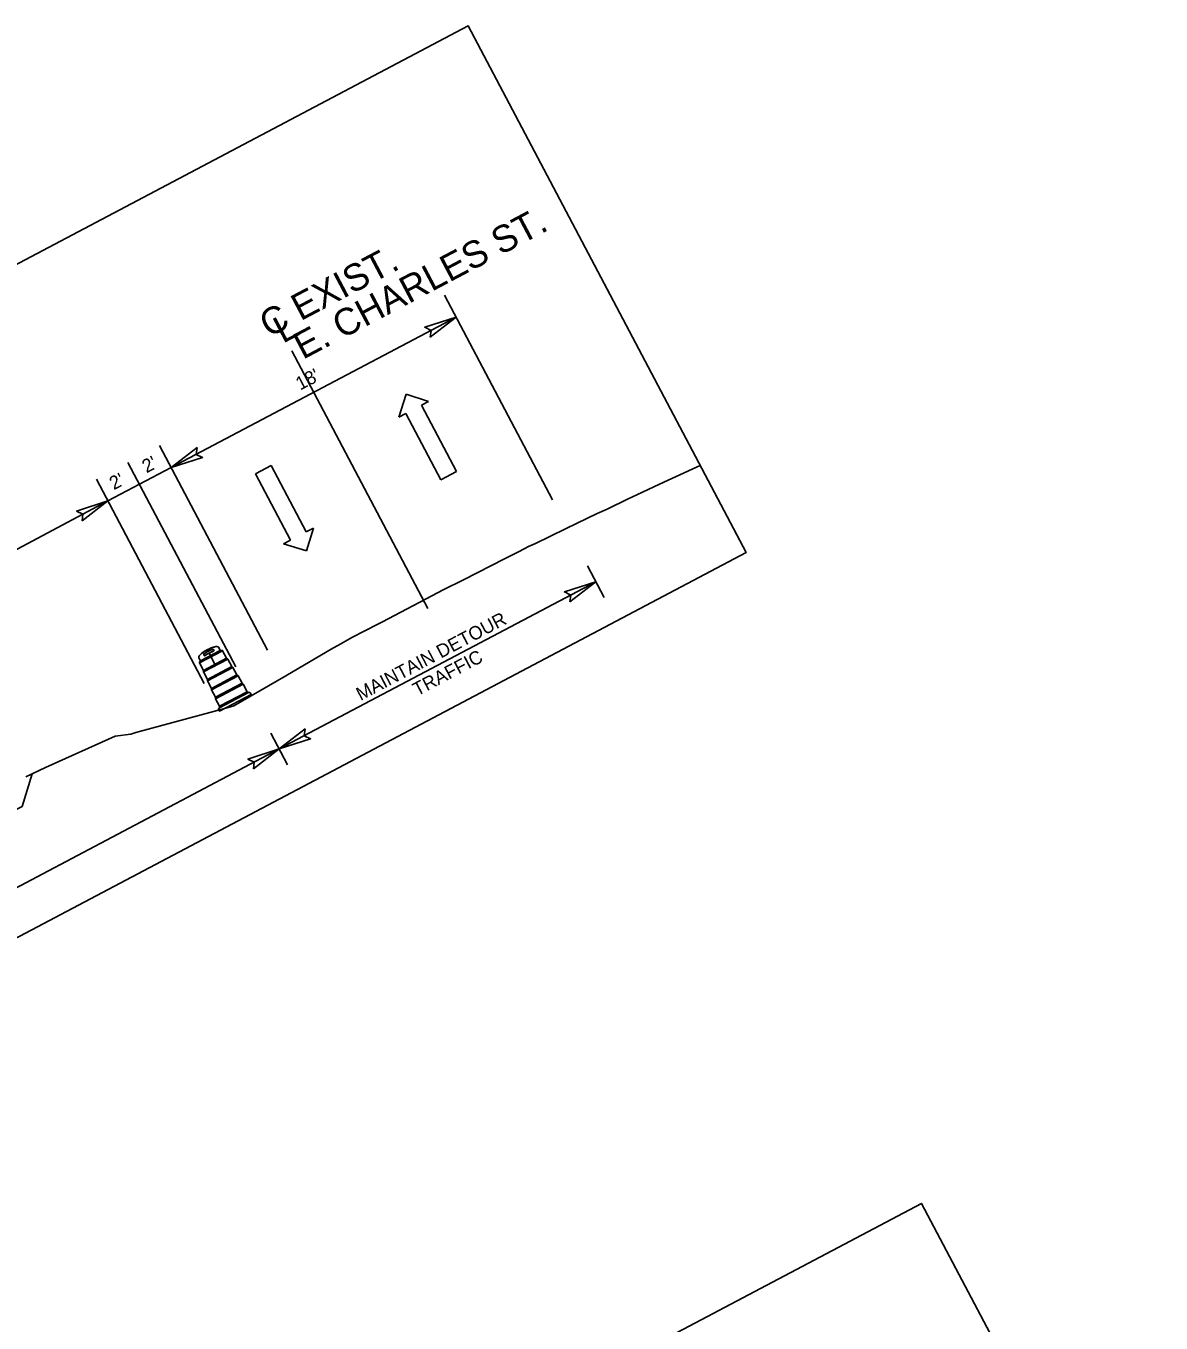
# Model space of a CAD drawing. Extents: x 1487176 to 1495274, y 497106 to 503692.
# Drawn here: x 1488752.5 to 1488815.9, y 497172.6 to 497245.1 of the extents above; entities that cross this region are included whole.
import ezdxf

# ---------------------------------------------------------------- set-up
doc = ezdxf.new("R2010")
doc.units = 0
for name, color, linetype in [('Default', 7, 'Continuous'), ('Exist XS Ground Line', 7, 'Continuous'), ('Prop Terminator CELL', 7, 'Continuous'), ('Typical Hinge Slope Interstate CELL', 7, 'Continuous'), ('WZ OSDR CELL', 7, 'Continuous')]:
    doc.layers.add(name, color=color, linetype=linetype)

msp = doc.modelspace()

# ---------------------------------------------------------------- linework, layer by layer
at = {"layer": 'Default'}
for p, q in [((1488781.918, 497218.598), (1488775.886, 497230.022)), ((1488776.533, 497228.797), (1488760.616, 497220.392)), ((1488774.953, 497212.514), (1488767.352, 497226.91)), ((1488773.735, 497224.49), (1488773.327, 497223.207)), ((1488774.999, 497224.089), (1488773.735, 497224.49)), ((1488774.601, 497223.879), (1488774.999, 497224.089)), ((1488776.562, 497220.165), (1488774.601, 497223.879)), ((1488773.327, 497223.207), (1488773.725, 497223.417)), ((1488773.725, 497223.417), (1488775.686, 497219.703)), ((1488766.001, 497210.193), (1488759.969, 497221.617)), ((1488764.232, 497209.259), (1488758.2, 497220.683)), ((1488758.847, 497219.459), (1488760.616, 497220.392)), ((1488765.325, 497220.05), (1488766.201, 497220.512)), ((1488767.286, 497216.336), (1488765.325, 497220.05)), ((1488766.201, 497220.512), (1488768.162, 497216.798)), ((1488775.686, 497219.703), (1488776.562, 497220.165)), ((1488762.464, 497208.325), (1488756.432, 497219.749)), ((1488757.078, 497218.525), (1488758.847, 497219.459)), ((1488757.078, 497218.525), (1488745.582, 497212.455)), ((1488766.888, 497216.126), (1488767.286, 497216.336)), ((1488768.162, 497216.798), (1488768.56, 497217.008)), ((1488768.56, 497217.008), (1488768.179, 497215.738)), ((1488768.179, 497215.738), (1488766.888, 497216.126)), ((1488784.808, 497213.125), (1488783.874, 497214.893)), ((1488784.341, 497214.009), (1488766.655, 497204.671)), ((1488767.122, 497203.786), (1488766.188, 497205.555)), ((1488766.655, 497204.671), (1488692.227, 497165.371))]:
    msp.add_line(p, q, dxfattribs=at)
for points in [[(1488676.518, 497191.898), (1488777.216, 497245.069), (1488792.751, 497215.648), (1488692.053, 497162.477)], [(1488710.97, 497130.93), (1488802.537, 497179.28), (1488815.927, 497153.921), (1488724.36, 497105.571)]]:
    msp.add_lwpolyline(points, close=True, dxfattribs=at)
msp.add_lwpolyline([(1488749.342, 497199.978), (1488752.289, 497201.459), (1488752.849, 497203.272)], dxfattribs=at)
at = {"layer": 'Exist XS Ground Line'}
msp.add_lwpolyline([(1488752.498, 497203.103), (1488753.584, 497203.626), (1488757.485, 497205.384), (1488758.354, 497205.487), (1488758.644, 497205.585), (1488763.673, 497206.94), (1488764.111, 497207.085), (1488767.017, 497208.753), (1488769.641, 497210.295), (1488769.971, 497210.474), (1488770.715, 497210.901), (1488772.153, 497211.635), (1488772.425, 497211.774), (1488773.09, 497212.124), (1488774.122, 497212.668), (1488774.541, 497212.89), (1488775.82, 497213.561), (1488776.94, 497214.124), (1488779.245, 497215.294), (1488780.067, 497215.709), (1488780.581, 497215.973), (1488780.962, 497216.15), (1488781.769, 497216.538), (1488782.693, 497216.983), (1488784.423, 497217.817), (1488784.967, 497218.076), (1488786.156, 497218.643), (1488786.64, 497218.872), (1488787.893, 497219.464), (1488788.585, 497219.789), (1488790.181, 497220.516)], dxfattribs=at)
at = {"layer": 'Prop Terminator CELL'}
for points in [[(1488775.086, 497227.682), (1488776.533, 497228.797), (1488774.783, 497228.235), (1488775.136, 497228.059)], [(1488762.062, 497221.507), (1488760.616, 497220.392), (1488762.366, 497220.955), (1488762.013, 497221.13)], [(1488755.631, 497217.41), (1488757.078, 497218.525), (1488755.328, 497217.962), (1488755.681, 497217.787)], [(1488782.894, 497212.895), (1488784.341, 497214.009), (1488782.591, 497213.447), (1488782.944, 497213.271)], [(1488768.102, 497205.785), (1488766.655, 497204.671), (1488768.405, 497205.233), (1488768.052, 497205.408)], [(1488765.208, 497203.556), (1488766.655, 497204.671), (1488764.905, 497204.108), (1488765.258, 497203.933)]]:
    msp.add_lwpolyline(points, close=True, dxfattribs=at)
at = {"layer": 'WZ OSDR CELL'}
for p, q in [((1488762.193, 497209.475), (1488763.489, 497210.159)), ((1488762.25, 497209.594), (1488763.359, 497210.179)), ((1488762.437, 497209.911), (1488762.434, 497209.917)), ((1488762.992, 497210.204), (1488762.989, 497210.209)), ((1488763.359, 497210.179), (1488763.291, 497210.309)), ((1488763.489, 497210.159), (1488763.709, 497209.744)), ((1488762.25, 497209.594), (1488762.182, 497209.723)), ((1488762.193, 497209.475), (1488762.413, 497209.059)), ((1488762.413, 497209.059), (1488763.709, 497209.744)), ((1488762.418, 497208.973), (1488763.777, 497209.691)), ((1488762.637, 497208.558), (1488763.996, 497209.275)), ((1488762.643, 497208.472), (1488764.064, 497209.223)), ((1488763.709, 497209.744), (1488763.777, 497209.691)), ((1488763.777, 497209.691), (1488763.996, 497209.275)), ((1488763.996, 497209.275), (1488764.064, 497209.223)), ((1488764.064, 497209.223), (1488764.284, 497208.807)), ((1488762.413, 497209.059), (1488762.418, 497208.973)), ((1488762.418, 497208.973), (1488762.637, 497208.558)), ((1488762.637, 497208.558), (1488762.643, 497208.472)), ((1488762.643, 497208.472), (1488762.862, 497208.056)), ((1488762.862, 497208.056), (1488764.284, 497208.807)), ((1488762.867, 497207.97), (1488764.352, 497208.754)), ((1488764.284, 497208.807), (1488764.352, 497208.754)), ((1488764.352, 497208.754), (1488764.571, 497208.339)), ((1488762.862, 497208.056), (1488762.867, 497207.97)), ((1488762.867, 497207.97), (1488763.087, 497207.555)), ((1488763.087, 497207.555), (1488764.571, 497208.339)), ((1488763.092, 497207.469), (1488764.639, 497208.286)), ((1488763.307, 497206.963), (1488764.936, 497207.822)), ((1488763.311, 497207.053), (1488764.859, 497207.87)), ((1488763.311, 497206.787), (1488765.078, 497207.72)), ((1488764.571, 497208.339), (1488764.639, 497208.286)), ((1488764.639, 497208.286), (1488764.859, 497207.87)), ((1488764.859, 497207.87), (1488764.927, 497207.818)), ((1488765.078, 497207.72), (1488765.042, 497207.79)), ((1488763.087, 497207.555), (1488763.092, 497207.469)), ((1488763.092, 497207.469), (1488763.311, 497207.053)), ((1488763.312, 497207.053), (1488763.317, 497206.967)), ((1488763.311, 497206.787), (1488763.275, 497206.857))]:
    msp.add_line(p, q, dxfattribs=at)
for points in [[(1488762.418, 497208.973), (1488763.097, 497209.332), (1488762.731, 497210.025), (1488762.698, 497210.008), (1488762.673, 497209.992), (1488762.647, 497209.978), (1488762.62, 497209.961), (1488762.592, 497209.943), (1488762.563, 497209.923), (1488762.531, 497209.902), (1488762.511, 497209.887), (1488762.497, 497209.882), (1488762.484, 497209.882), (1488762.47, 497209.884), (1488762.459, 497209.889), (1488762.449, 497209.896), (1488762.441, 497209.904), (1488762.431, 497209.923), (1488762.428, 497209.935), (1488762.429, 497209.95), (1488762.433, 497209.964), (1488762.441, 497209.978), (1488762.45, 497209.986), (1488762.474, 497210.003), (1488762.505, 497210.025), (1488762.571, 497210.069), (1488762.62, 497210.098), (1488762.657, 497210.118), (1488762.677, 497210.129), (1488762.631, 497210.216), (1488762.595, 497210.197), (1488762.549, 497210.171), (1488762.503, 497210.143), (1488762.455, 497210.111), (1488762.411, 497210.079), (1488762.363, 497210.043), (1488762.31, 497210), (1488762.279, 497209.973), (1488762.231, 497209.928), (1488762.21, 497209.908), (1488762.198, 497209.894), (1488762.186, 497209.877), (1488762.176, 497209.858), (1488762.168, 497209.831), (1488762.164, 497209.808), (1488762.164, 497209.788), (1488762.167, 497209.767), (1488762.172, 497209.747), (1488762.182, 497209.723), (1488762.25, 497209.594), (1488762.241, 497209.582), (1488762.232, 497209.569), (1488762.22, 497209.549), (1488762.21, 497209.528), (1488762.202, 497209.508), (1488762.193, 497209.475), (1488762.413, 497209.059)], [(1488763.777, 497209.691), (1488763.097, 497209.332), (1488762.731, 497210.025), (1488762.79, 497210.055), (1488762.832, 497210.074), (1488762.868, 497210.09), (1488762.899, 497210.102), (1488762.933, 497210.116), (1488762.962, 497210.126), (1488762.975, 497210.132), (1488762.985, 497210.141), (1488762.993, 497210.155), (1488762.997, 497210.17), (1488762.998, 497210.184), (1488762.995, 497210.197), (1488762.989, 497210.209), (1488762.978, 497210.224), (1488762.963, 497210.234), (1488762.952, 497210.237), (1488762.941, 497210.238), (1488762.932, 497210.238), (1488762.922, 497210.236), (1488762.897, 497210.227), (1488762.872, 497210.217), (1488762.847, 497210.207), (1488762.821, 497210.197), (1488762.789, 497210.183), (1488762.754, 497210.168), (1488762.727, 497210.155), (1488762.704, 497210.143), (1488762.677, 497210.129), (1488762.631, 497210.216), (1488762.671, 497210.237), (1488762.704, 497210.253), (1488762.75, 497210.273), (1488762.781, 497210.287), (1488762.817, 497210.301), (1488762.857, 497210.317), (1488762.905, 497210.333), (1488762.953, 497210.348), (1488763.011, 497210.364), (1488763.06, 497210.376), (1488763.102, 497210.386), (1488763.122, 497210.389), (1488763.141, 497210.392), (1488763.162, 497210.392), (1488763.184, 497210.39), (1488763.2, 497210.384), (1488763.22, 497210.377), (1488763.237, 497210.367), (1488763.254, 497210.355), (1488763.267, 497210.343), (1488763.279, 497210.328), (1488763.287, 497210.315), (1488763.291, 497210.309), (1488763.359, 497210.179), (1488763.391, 497210.181), (1488763.408, 497210.18), (1488763.426, 497210.177), (1488763.446, 497210.174), (1488763.469, 497210.167), (1488763.481, 497210.163), (1488763.489, 497210.159), (1488763.709, 497209.744)], [(1488762.637, 497208.558), (1488763.996, 497209.275), (1488764.064, 497209.223), (1488764.284, 497208.807), (1488764.352, 497208.754), (1488762.867, 497207.97), (1488762.862, 497208.056), (1488762.643, 497208.472)], [(1488763.087, 497207.555), (1488764.571, 497208.339), (1488764.639, 497208.286), (1488764.859, 497207.87), (1488764.927, 497207.818), (1488764.944, 497207.827), (1488764.956, 497207.83), (1488764.972, 497207.831), (1488764.988, 497207.83), (1488764.999, 497207.827), (1488765.012, 497207.821), (1488765.024, 497207.812), (1488765.032, 497207.804), (1488765.038, 497207.796), (1488765.042, 497207.79), (1488765.078, 497207.72), (1488763.311, 497206.787), (1488763.275, 497206.857), (1488763.27, 497206.867), (1488763.267, 497206.879), (1488763.266, 497206.892), (1488763.266, 497206.903), (1488763.268, 497206.913), (1488763.273, 497206.927), (1488763.281, 497206.939), (1488763.29, 497206.95), (1488763.296, 497206.956), (1488763.307, 497206.963), (1488763.317, 497206.967), (1488763.312, 497207.053), (1488763.092, 497207.469)]]:
    msp.add_lwpolyline(points, close=True, dxfattribs=at)
for centre, radius, start, end in [((1488762.321, 497209.796), 0.157, 134.78432, 207.8351), ((1488763.456, 497208.652), 1.769, 100.88588, 134.78432), ((1488762.483, 497209.942), 0.0548, 126.50911, 207.8351), ((1488762.486, 497209.936), 0.0548, 207.8351, 305.98385), ((1488763.503, 497208.565), 1.769, 109.16109, 126.50911), ((1488763.558, 497208.461), 1.769, 109.68635, 125.98385), ((1488762.94, 497210.184), 0.0548, 27.8351, 109.16109), ((1488762.943, 497210.178), 0.0548, 289.68635, 27.8351), ((1488763.152, 497210.235), 0.157, 27.8351, 100.88588), ((1488763.385, 497209.91), 0.271, 67.32155, 95.52908), ((1488762.458, 497209.42), 0.271, 140.14111, 168.34864), ((1488764.972, 497207.753), 0.0783, 27.8351, 117.8351), ((1488763.344, 497206.893), 0.0783, 117.8351, 207.8351)]:
    msp.add_arc(centre, radius, start, end, dxfattribs=at)

# ---------------------------------------------------------------- texts
at = {"layer": 'Default'}
for s, p in [("18'", (1488767.82, 497224.689)), ("2'", (1488759.236, 497220.066)), ("2'", (1488757.412, 497219.123)), ('MAINTAIN DETOUR', (1488771.199, 497207.347)), ('TRAFFIC', (1488774.362, 497207.604))]:
    msp.add_text(s, height=0.75, rotation=27.83509, dxfattribs=at).set_placement(p)
at = {"layer": 'Typical Hinge Slope Interstate CELL'}
for s, p in [('  E. CHARLES ST.', (1488766.986, 497225.887)), ('C EXIST.', (1488766.068, 497227.626)), ('L', (1488766.849, 497227.305))]:
    msp.add_text(s, height=1.5, rotation=27.83509, dxfattribs=at).set_placement(p)

doc.saveas('drawing.dxf')
